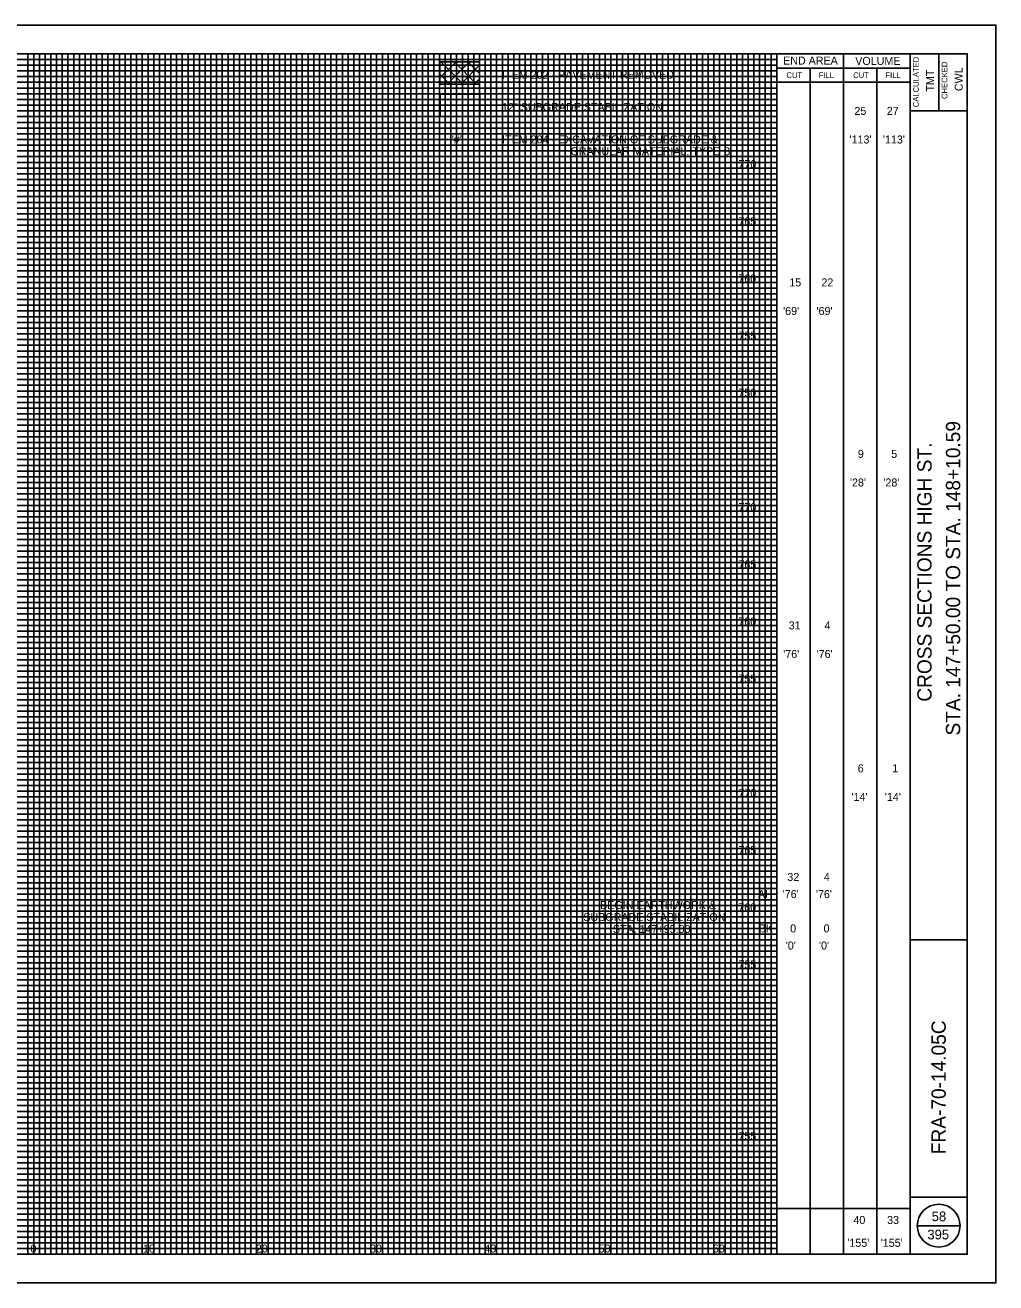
# Model space of a CAD drawing. Extents: x -10 to 160, y -2 to 568.
# Drawn here: x 75.1 to 160, y -2.5 to 107.5 of the extents above; entities that cross this region are included whole.
import ezdxf

# ---------------------------------------------------------------- set-up
doc = ezdxf.new("R2010")
doc.units = 0
for name, color, linetype in [('DR_P_Text', 7, 'Continuous'), ('SV_X_Text_Comment', 7, 'Continuous'), ('SV_X_Text_Elevation', 7, 'Continuous'), ('XS_P_Annotation', 7, 'Continuous'), ('XS_P_Finished_Grade', 7, 'Continuous'), ('XS_P_Pavt_Layers', 7, 'Continuous'), ('XS_P_Shoulder_Surface', 7, 'Continuous'), ('XS_P_Subgrade', 7, 'Continuous'), ('XS_P_Text_MarkedPoint', 7, 'Continuous')]:
    doc.layers.add(name, color=color, linetype=linetype)

msp = doc.modelspace()

# ---------------------------------------------------------------- linework, layer by layer
at = {"layer": 'SV_X_Text_Comment'}
msp.add_lwpolyline([(-10, -2.5), (160, -2.5), (160, 107.5), (-10, 107.5)], close=True, dxfattribs=at)
at = {"layer": 'SV_X_Text_Elevation'}
for p, q in [((75.33, 0), (75.33, 105)), ((76.33, 0), (76.33, 105)), ((76.83, 0), (76.83, 105)), ((77.33, 0), (77.33, 105)), ((77.83, 0), (77.83, 105)), ((78.33, 0), (78.33, 105)), ((78.83, 0), (78.83, 105)), ((79.33, 0), (79.33, 105)), ((79.83, 0), (79.83, 105)), ((80.33, 0), (80.33, 105)), ((81.33, 0), (81.33, 105)), ((81.83, 0), (81.83, 105)), ((82.33, 0), (82.33, 105)), ((82.83, 0), (82.83, 105)), ((83.33, 0), (83.33, 105)), ((83.83, 0), (83.83, 105)), ((84.33, 0), (84.33, 105)), ((84.83, 0), (84.83, 105)), ((85.33, 0), (85.33, 105)), ((86.33, 0), (86.33, 105)), ((86.83, 0), (86.83, 105)), ((87.33, 0), (87.33, 105)), ((87.83, 0), (87.83, 105)), ((88.33, 0), (88.33, 105)), ((88.83, 0), (88.83, 105)), ((89.33, 0), (89.33, 105)), ((89.83, 0), (89.83, 105)), ((90.33, 0), (90.33, 105)), ((91.33, 0), (91.33, 105)), ((91.83, 0), (91.83, 105)), ((92.33, 0), (92.33, 105)), ((92.83, 0), (92.83, 105)), ((93.33, 0), (93.33, 105)), ((93.83, 0), (93.83, 105)), ((94.33, 0), (94.33, 105)), ((94.83, 0), (94.83, 105)), ((95.33, 0), (95.33, 105)), ((96.33, 0), (96.33, 105)), ((96.83, 0), (96.83, 105)), ((97.33, 0), (97.33, 105)), ((97.83, 0), (97.83, 105)), ((98.33, 0), (98.33, 105)), ((98.83, 0), (98.83, 105)), ((99.33, 0), (99.33, 105)), ((99.83, 0), (99.83, 105)), ((100.33, 0), (100.33, 105)), ((101.33, 0), (101.33, 105)), ((101.83, 0), (101.83, 105)), ((102.33, 0), (102.33, 105)), ((102.83, 0), (102.83, 105)), ((103.33, 0), (103.33, 105)), ((103.83, 0), (103.83, 105)), ((104.33, 0), (104.33, 105)), ((104.83, 0), (104.83, 105)), ((105.33, 0), (105.33, 105)), ((106.33, 0), (106.33, 105)), ((106.83, 0), (106.83, 105)), ((107.33, 0), (107.33, 105)), ((107.83, 0), (107.83, 105)), ((108.33, 0), (108.33, 105)), ((108.83, 0), (108.83, 105)), ((109.33, 0), (109.33, 105)), ((109.83, 0), (109.83, 105)), ((110.33, 0), (110.33, 105)), ((111.33, 0), (111.33, 105)), ((111.83, 0), (111.83, 105)), ((112.33, 0), (112.33, 105)), ((112.83, 0), (112.83, 105)), ((113.33, 0), (113.33, 105)), ((113.83, 0), (113.83, 105)), ((114.33, 0), (114.33, 105)), ((114.83, 0), (114.83, 105)), ((115.33, 0), (115.33, 105)), ((116.33, 0), (116.33, 105)), ((116.83, 0), (116.83, 105)), ((117.33, 0), (117.33, 105)), ((117.83, 0), (117.83, 105)), ((118.33, 0), (118.33, 105)), ((118.83, 0), (118.83, 105)), ((119.33, 0), (119.33, 105)), ((119.83, 0), (119.83, 105)), ((120.33, 0), (120.33, 105)), ((121.33, 0), (121.33, 105)), ((121.83, 0), (121.83, 105)), ((122.33, 0), (122.33, 105)), ((122.83, 0), (122.83, 105)), ((123.33, 0), (123.33, 105)), ((123.83, 0), (123.83, 105)), ((124.33, 0), (124.33, 105)), ((124.83, 0), (124.83, 105)), ((125.33, 0), (125.33, 105)), ((126.33, 0), (126.33, 105)), ((126.83, 0), (126.83, 105)), ((127.33, 0), (127.33, 105)), ((127.83, 0), (127.83, 105)), ((128.33, 0), (128.33, 105)), ((128.83, 0), (128.83, 105)), ((129.33, 0), (129.33, 105)), ((129.83, 0), (129.83, 105)), ((130.33, 0), (130.33, 105)), ((131.33, 0), (131.33, 105)), ((131.83, 0), (131.83, 105)), ((132.33, 0), (132.33, 105)), ((132.83, 0), (132.83, 105)), ((133.33, 0), (133.33, 105)), ((133.83, 0), (133.83, 105)), ((134.33, 0), (134.33, 105)), ((134.83, 0), (134.83, 105)), ((135.33, 0), (135.33, 105)), ((136.33, 0), (136.33, 105)), ((136.83, 0), (136.83, 105)), ((137.33, 0), (137.33, 105)), ((137.83, 0), (137.83, 105)), ((138.33, 0), (138.33, 105)), ((138.83, 0), (138.83, 105)), ((139.33, 0), (139.33, 105)), ((139.83, 0), (139.83, 105)), ((140.33, 0), (140.33, 105)), ((5.83, 104.5), (140.83, 104.5)), ((5.83, 104), (140.83, 104)), ((5.83, 103.5), (140.83, 103.5)), ((5.83, 103), (140.83, 103)), ((5.83, 102.5), (140.83, 102.5)), ((5.83, 102), (140.83, 102)), ((5.83, 101.5), (140.83, 101.5)), ((5.83, 101), (140.83, 101)), ((5.83, 100.5), (140.83, 100.5)), ((5.83, 99.5), (140.83, 99.5)), ((5.83, 99), (140.83, 99)), ((5.83, 98.5), (140.83, 98.5)), ((5.83, 98), (140.83, 98)), ((5.83, 97.5), (140.83, 97.5)), ((5.83, 97), (140.83, 97)), ((5.83, 96.5), (140.83, 96.5)), ((5.83, 96), (140.83, 96)), ((5.83, 95.5), (140.83, 95.5)), ((5.83, 94.5), (140.83, 94.5)), ((5.83, 94), (140.83, 94)), ((5.83, 93.5), (140.83, 93.5)), ((5.83, 93), (140.83, 93)), ((5.83, 92.5), (140.83, 92.5)), ((5.83, 92), (140.83, 92)), ((5.83, 91.5), (140.83, 91.5)), ((5.83, 91), (140.83, 91)), ((5.83, 90.5), (140.83, 90.5)), ((5.83, 89.5), (140.83, 89.5)), ((5.83, 89), (140.83, 89)), ((5.83, 88.5), (140.83, 88.5)), ((5.83, 88), (140.83, 88)), ((5.83, 87.5), (140.83, 87.5)), ((5.83, 87), (140.83, 87)), ((5.83, 86.5), (140.83, 86.5)), ((5.83, 86), (140.83, 86)), ((5.83, 85.5), (140.83, 85.5)), ((5.83, 84.5), (140.83, 84.5)), ((5.83, 84), (140.83, 84)), ((5.83, 83.5), (140.83, 83.5)), ((5.83, 83), (140.83, 83)), ((5.83, 82.5), (140.83, 82.5)), ((5.83, 82), (140.83, 82)), ((5.83, 81.5), (140.83, 81.5)), ((5.83, 81), (140.83, 81)), ((5.83, 80.5), (140.83, 80.5)), ((5.83, 79.5), (140.83, 79.5)), ((5.83, 79), (140.83, 79)), ((5.83, 78.5), (140.83, 78.5)), ((5.83, 78), (140.83, 78)), ((5.83, 77.5), (140.83, 77.5)), ((5.83, 77), (140.83, 77)), ((5.83, 76.5), (140.83, 76.5)), ((5.83, 76), (140.83, 76)), ((5.83, 75.5), (140.83, 75.5)), ((5.83, 74.5), (140.83, 74.5)), ((5.83, 74), (140.83, 74)), ((5.83, 73.5), (140.83, 73.5)), ((5.83, 73), (140.83, 73)), ((5.83, 72.5), (140.83, 72.5)), ((5.83, 72), (140.83, 72)), ((5.83, 71.5), (140.83, 71.5)), ((5.83, 71), (140.83, 71)), ((5.83, 70.5), (140.83, 70.5)), ((5.83, 69.5), (140.83, 69.5)), ((5.83, 69), (140.83, 69)), ((5.83, 68.5), (140.83, 68.5)), ((5.83, 68), (140.83, 68)), ((5.83, 67.5), (140.83, 67.5)), ((5.83, 67), (140.83, 67)), ((5.83, 66.5), (140.83, 66.5)), ((5.83, 66), (140.83, 66)), ((5.83, 65.5), (140.83, 65.5)), ((5.83, 64.5), (140.83, 64.5)), ((5.83, 64), (140.83, 64)), ((5.83, 63.5), (140.83, 63.5)), ((5.83, 63), (140.83, 63)), ((5.83, 62.5), (140.83, 62.5)), ((5.83, 62), (140.83, 62)), ((5.83, 61.5), (140.83, 61.5)), ((5.83, 61), (140.83, 61)), ((5.83, 60.5), (140.83, 60.5)), ((5.83, 59.5), (140.83, 59.5)), ((5.83, 59), (140.83, 59)), ((5.83, 58.5), (140.83, 58.5)), ((5.83, 58), (140.83, 58)), ((5.83, 57.5), (140.83, 57.5)), ((5.83, 57), (140.83, 57)), ((5.83, 56.5), (140.83, 56.5)), ((5.83, 56), (140.83, 56)), ((5.83, 55.5), (140.83, 55.5)), ((5.83, 54.5), (140.83, 54.5)), ((5.83, 54), (140.83, 54)), ((5.83, 53.5), (140.83, 53.5)), ((5.83, 53), (140.83, 53)), ((5.83, 52.5), (140.83, 52.5)), ((5.83, 52), (140.83, 52)), ((5.83, 51.5), (140.83, 51.5)), ((5.83, 51), (140.83, 51)), ((5.83, 50.5), (140.83, 50.5)), ((5.83, 49.5), (140.83, 49.5)), ((5.83, 49), (140.83, 49)), ((5.83, 48.5), (140.83, 48.5)), ((5.83, 48), (140.83, 48)), ((5.83, 47.5), (140.83, 47.5)), ((5.83, 47), (140.83, 47)), ((5.83, 46.5), (140.83, 46.5)), ((5.83, 46), (140.83, 46)), ((5.83, 45.5), (140.83, 45.5)), ((5.83, 44.5), (140.83, 44.5)), ((5.83, 44), (140.83, 44)), ((5.83, 43.5), (140.83, 43.5)), ((5.83, 43), (140.83, 43)), ((5.83, 42.5), (140.83, 42.5)), ((5.83, 42), (140.83, 42)), ((5.83, 41.5), (140.83, 41.5)), ((5.83, 41), (140.83, 41)), ((5.83, 40.5), (140.83, 40.5)), ((5.83, 39.5), (140.83, 39.5)), ((5.83, 39), (140.83, 39)), ((5.83, 38.5), (140.83, 38.5)), ((5.83, 38), (140.83, 38)), ((5.83, 37.5), (140.83, 37.5)), ((5.83, 37), (140.83, 37)), ((5.83, 36.5), (140.83, 36.5)), ((5.83, 36), (140.83, 36)), ((5.83, 35.5), (140.83, 35.5)), ((5.83, 34.5), (140.83, 34.5)), ((5.83, 34), (140.83, 34)), ((5.83, 33.5), (140.83, 33.5)), ((5.83, 33), (140.83, 33)), ((5.83, 32.5), (140.83, 32.5)), ((5.83, 32), (140.83, 32)), ((5.83, 31.5), (140.83, 31.5)), ((5.83, 31), (140.83, 31)), ((5.83, 30.5), (140.83, 30.5)), ((5.83, 29.5), (140.83, 29.5)), ((5.83, 29), (140.83, 29)), ((5.83, 28.5), (140.83, 28.5)), ((5.83, 28), (140.83, 28)), ((5.83, 27.5), (140.83, 27.5)), ((5.83, 27), (140.83, 27)), ((5.83, 26.5), (140.83, 26.5)), ((5.83, 26), (140.83, 26)), ((5.83, 25.5), (140.83, 25.5)), ((5.83, 24.5), (140.83, 24.5)), ((5.83, 24), (140.83, 24)), ((5.83, 23.5), (140.83, 23.5)), ((5.83, 23), (140.83, 23)), ((5.83, 22.5), (140.83, 22.5)), ((5.83, 22), (140.83, 22)), ((5.83, 21.5), (140.83, 21.5)), ((5.83, 21), (140.83, 21)), ((5.83, 20.5), (140.83, 20.5)), ((5.83, 19.5), (140.83, 19.5)), ((5.83, 19), (140.83, 19)), ((5.83, 18.5), (140.83, 18.5)), ((5.83, 18), (140.83, 18)), ((5.83, 17.5), (140.83, 17.5)), ((5.83, 17), (140.83, 17)), ((5.83, 16.5), (140.83, 16.5)), ((5.83, 16), (140.83, 16)), ((5.83, 15.5), (140.83, 15.5)), ((5.83, 14.5), (140.83, 14.5)), ((5.83, 14), (140.83, 14)), ((5.83, 13.5), (140.83, 13.5)), ((5.83, 13), (140.83, 13)), ((5.83, 12.5), (140.83, 12.5)), ((5.83, 12), (140.83, 12)), ((5.83, 11.5), (140.83, 11.5)), ((5.83, 11), (140.83, 11)), ((5.83, 10.5), (140.83, 10.5)), ((5.83, 9.5), (140.83, 9.5)), ((5.83, 9), (140.83, 9)), ((5.83, 8.5), (140.83, 8.5)), ((5.83, 8), (140.83, 8)), ((5.83, 7.5), (140.83, 7.5)), ((5.83, 7), (140.83, 7)), ((5.83, 6.5), (140.83, 6.5)), ((5.83, 6), (140.83, 6)), ((5.83, 5.5), (140.83, 5.5)), ((5.83, 4.5), (140.83, 4.5)), ((5.83, 4), (140.83, 4)), ((5.83, 3.5), (140.83, 3.5)), ((5.83, 3), (140.83, 3)), ((5.83, 2.5), (140.83, 2.5)), ((5.83, 2), (140.83, 2)), ((5.83, 1.5), (140.83, 1.5)), ((5.83, 1), (140.83, 1)), ((5.83, 0.5), (140.83, 0.5))]:
    msp.add_line(p, q, dxfattribs=at)
at = {"layer": 'XS_P_Annotation'}
for p, q in [((152.5, 0), (152.5, 105)), ((155, 105), (155, 100)), ((152.5, 100), (157.5, 100)), ((152.5, 27.5), (157.5, 27.5)), ((152.5, 5), (157.5, 5))]:
    msp.add_line(p, q, dxfattribs=at)
msp.add_lwpolyline([(0, 105), (157.5, 105), (157.5, 0), (0, 0)], close=True, dxfattribs=at)
at = {"layer": 'XS_P_Finished_Grade'}
for p, q in [((140.83, 0), (140.83, 105)), ((146.67, 0), (146.67, 105)), ((140.83, 103.75), (152.5, 103.75)), ((143.75, 0), (143.75, 103.75)), ((149.58, 0), (149.58, 103.75)), ((140.83, 102.5), (152.5, 102.5)), ((140.83, 4), (152.5, 4)), ((153.12, 2.5), (156.88, 2.5)), ((142.29, 1), (142.29, 1)), ((145.21, 1), (145.21, 1)), ((148.12, 1), (148.12, 1)), ((151.04, 1), (151.04, 1))]:
    msp.add_line(p, q, dxfattribs=at)
msp.add_circle((155, 2.5), 1.87, dxfattribs=at)
at = {"layer": 'XS_P_Pavt_Layers'}
for p, q in [((111.36, 102.88), (112.78, 104.3)), ((111.45, 104.3), (113.39, 102.35)), ((112.01, 102.35), (113.96, 104.3)), ((112.63, 104.3), (114.57, 102.35)), ((113.19, 102.35), (114.83, 103.99)), ((113.81, 104.3), (114.83, 103.28)), ((111.36, 103.21), (112.22, 102.35)), ((114.37, 102.35), (114.83, 102.81))]:
    msp.add_line(p, q, dxfattribs=at)
at = {"layer": 'XS_P_Shoulder_Surface'}
msp.add_lwpolyline([(111.39, 99.52), (114.86, 99.52), (114.86, 101.47), (111.39, 101.47), (111.39, 99.52)], dxfattribs=at)
at = {"layer": 'XS_P_Subgrade'}
for points in [[(111.36, 104.3), (114.83, 104.3), (114.83, 102.35), (111.36, 102.35)], [(111.39, 101.47), (114.86, 101.47), (114.86, 99.52), (111.39, 99.52)]]:
    msp.add_lwpolyline(points, close=True, dxfattribs=at)
at = {"layer": 'XS_P_Text_MarkedPoint'}
for p, q in [((75.83, 0), (75.83, 105)), ((80.83, 0), (80.83, 105)), ((85.83, 0), (85.83, 105)), ((90.83, 0), (90.83, 105)), ((95.83, 0), (95.83, 105)), ((100.83, 0), (100.83, 105)), ((105.83, 0), (105.83, 105)), ((110.83, 0), (110.83, 105)), ((115.83, 0), (115.83, 105)), ((120.83, 0), (120.83, 105)), ((125.83, 0), (125.83, 105)), ((130.83, 0), (130.83, 105)), ((135.83, 0), (135.83, 105)), ((5.83, 100), (140.83, 100)), ((5.83, 95), (140.83, 95)), ((5.83, 90), (140.83, 90)), ((5.83, 85), (140.83, 85)), ((5.83, 80), (140.83, 80)), ((5.83, 75), (140.83, 75)), ((5.83, 70), (140.83, 70)), ((5.83, 65), (140.83, 65)), ((5.83, 60), (140.83, 60)), ((5.83, 55), (140.83, 55)), ((5.83, 50), (140.83, 50)), ((5.83, 45), (140.83, 45)), ((5.83, 40), (140.83, 40)), ((5.83, 35), (140.83, 35)), ((5.83, 30), (140.83, 30)), ((5.83, 25), (140.83, 25)), ((5.83, 20), (140.83, 20)), ((5.83, 15), (140.83, 15)), ((5.83, 10), (140.83, 10)), ((5.83, 5), (140.83, 5))]:
    msp.add_line(p, q, dxfattribs=at)

# ---------------------------------------------------------------- texts
at = {"layer": 'DR_P_Text'}
for s, p in [('25', (147.63, 99.65)), ('27', (150.46, 99.65)), ("'#'", (112.4, 97.16)), ("'113'", (147.2, 97.15)), ("'113'", (150.12, 97.15)), ('770', (137.48, 95)), ('765', (137.48, 90)), ('760', (137.47, 85)), ('15', (141.93, 84.65)), ('22', (144.74, 84.65)), ("'69'", (141.39, 82.15)), ("'69'", (144.31, 82.15)), ('755', (137.48, 80)), ('750', (137.47, 75)), ('9', (147.93, 69.65)), ('5', (150.85, 69.65)), ("'28'", (147.24, 67.15)), ("'28'", (150.16, 67.15)), ('770', (137.48, 65)), ('765', (137.48, 60)), ('760', (137.47, 55)), ('31', (141.88, 54.65)), ('4', (145.01, 54.65)), ("'76'", (141.4, 52.15)), ("'76'", (144.32, 52.15)), ('755', (137.48, 50)), ('6', (147.92, 42.15)), ('1', (150.94, 42.15)), ('770', (137.48, 40)), ("'14'", (147.37, 39.65)), ("'14'", (150.29, 39.65)), ('765', (137.48, 35)), ('32', (141.76, 32.65)), ('4', (144.95, 32.65)), ('AH', (139.19, 31.15)), ("'76'", (141.35, 31.15)), ("'76'", (144.26, 31.15)), ('760', (137.47, 30)), ('BK', (139.26, 28.15)), ('0', (142.01, 28.15)), ('0', (144.93, 28.15)), ("'0'", (141.62, 26.65)), ("'0'", (144.53, 26.65)), ('755', (137.48, 25)), ('755', (137.48, 10)), ('40', (147.54, 2.65)), ('33', (150.49, 2.65)), ("'155'", (147.01, 0.65)), ("'155'", (149.93, 0.65)), ('0', (75.55, 0.15)), ('0', (75.55, 0.15)), ('10', (85.39, 0.15)), ('20', (95.26, 0.15)), ('30', (105.25, 0.15)), ('40', (115.25, 0.15)), ('50', (125.25, 0.15)), ('60', (135.25, 0.15))]:
    msp.add_text(s, height=0.7, dxfattribs=at).set_placement(p)
at = {"layer": 'XS_P_Finished_Grade'}
for s, height, p in [('END AREA', 0.7, (141.39, 104.05)), ('VOLUME', 0.7, (147.7, 104.02)), ('CUT', 0.5, (141.68, 102.87)), ('FILL', 0.5, (144.5, 102.87)), ('CUT', 0.5, (147.52, 102.87)), ('FILL', 0.5, (150.34, 102.87)), ('58', 0.85, (154.39, 2.89)), ('395', 0.85, (154.01, 1.3))]:
    msp.add_text(s, height=height, dxfattribs=at).set_placement(p)
for s, height, p in [('CALCULATED', 0.5, (153.26, 100.32)), ('TMT', 0.7, (154.6, 101.69)), ('CHECKED', 0.5, (155.76, 101.04)), ('CWL', 0.7, (157.1, 101.73)), ('STA. 147+50.00 TO STA. 148+10.59', 1.25, (156.88, 45.37)), ('CROSS SECTIONS HIGH ST.', 1.25, (154.38, 48.33)), ('FRA-70-14.05C', 1.25, (155.62, 8.75))]:
    msp.add_text(s, height=height, rotation=90, dxfattribs=at).set_placement(p)
at = {"layer": 'XS_P_Subgrade'}
for s, p in [('ITEM 202 - PAVEMENT REMOVED', (116.81, 102.81)), ('12" SUBGRADE STABILIZATION', (116.81, 99.99)), ('ITEM 204 - EXCAVATION OF SUBGRADE &', (116.81, 97.16)), ('GRANULAR MATERIAL, TYPE B', (122.79, 96.12)), ('BEGIN EARTHWORK &', (125.38, 30.19)), ('SUBGRADE STABILIZATION', (123.91, 29.14)), ('STA. 147+95.00', (126.5, 28.1))]:
    msp.add_text(s, height=0.7, dxfattribs=at).set_placement(p)

doc.saveas('drawing.dxf')
